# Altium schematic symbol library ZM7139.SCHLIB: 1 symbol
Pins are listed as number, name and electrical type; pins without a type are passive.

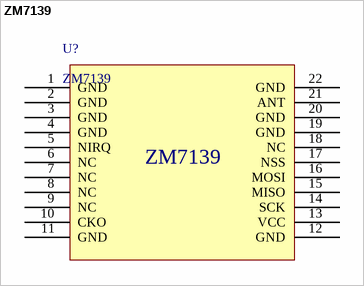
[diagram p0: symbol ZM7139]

## ZM7139
designator U?
pins: 1 GND, 2 GND, 3 GND, 4 GND, 5 NIRQ, 6 NC, 7 NC, 8 NC, 9 NC, 10 CKO, 11 GND, 12 GND, 13 VCC, 14 SCK, 15 MISO, 16 MOSI, 17 NSS, 18 NC, 19 GND, 20 GND, 21 ANT, 22 GND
